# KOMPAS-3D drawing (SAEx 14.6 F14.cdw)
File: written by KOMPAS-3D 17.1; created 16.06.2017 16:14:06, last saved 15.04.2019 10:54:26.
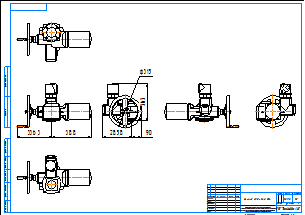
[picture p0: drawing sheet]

Sheet 1: A2, landscape

Title block, sheet 1: name: Привод SAEx 14.6 F14; material: Внимание! Данный продукт является объектом авторского права ООО «Торговый Дом АДЛ». / Запрещается изменение, копирование, распространение / (в том числе путем копирования на другие сайты и ресурсы в Интернете) / или любое иное использование информации и объектов без предварительного / согласия правообладателя (ООО «Торговый Дом АДЛ»).; mass: 129,8; sheets: 1; organisation: ООО "Торговый дом АДЛ"; sheet format: A2; stored path: \\adlc.lan\data\АДЛ_ПКД\3D-модели\Поставщики\Сервоприводы AUMA\Электроприводы серии SA\KOMPAS 2D\Привод SAEx 14.6 F14.cdw

Views: Спереди 1, Проекционный вид 2, Проекционный вид 3, Проекционный вид 4, Проекционный вид 5, Проекционный вид 6
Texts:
  Klimkovich
  ADL
Dimensions and other numbers on the sheet: 363; 90; 285,8; 336,3; 388; 1:5; 1; 129,8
